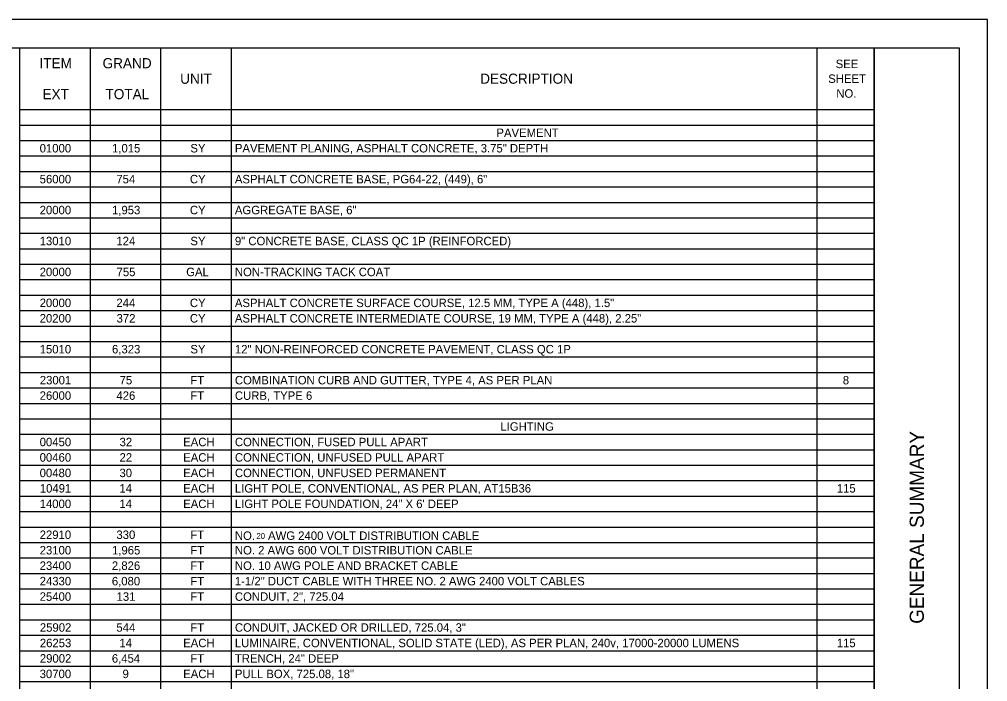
# Model space of a CAD drawing. Extents: x 0 to 34, y 0 to 22.
# Drawn here: x 16.92 to 34, y 10.33 to 22 of the extents above; entities that cross this region are included whole.
import ezdxf

# ---------------------------------------------------------------- set-up
doc = ezdxf.new("R2010")
doc.units = 0
for name, color, linetype in [('SH_Border', 7, 'Continuous'), ('SH_Cut_Line', 7, 'Continuous'), ('SH_Data', 7, 'Continuous'), ('SH_Text', 7, 'Continuous')]:
    doc.layers.add(name, color=color, linetype=linetype)

msp = doc.modelspace()

# ---------------------------------------------------------------- linework, layer by layer
at = {"layer": 'SH_Border'}
msp.add_line((32, 0.5), (32, 21.5), dxfattribs=at)
msp.add_lwpolyline([(1.5, 21.5), (33.5, 21.5), (33.5, 0.5), (1.5, 0.5)], close=True, dxfattribs=at)
at = {"layer": 'SH_Cut_Line'}
msp.add_lwpolyline([(0, 0), (34, 0), (34, 22), (0, 22)], close=True, dxfattribs=at)
at = {"layer": 'SH_Text'}
for p, q in [((16.919, 21.5), (19.411, 21.5)), ((16.919, 21.5), (16.919, 21.227)), ((18.165, 21.5), (18.165, 21.227)), ((19.411, 21.5), (20.657, 21.5)), ((19.411, 21.5), (19.411, 21.227)), ((20.657, 21.5), (32, 21.5)), ((20.657, 21.5), (20.657, 21.227)), ((30.988, 21.5), (30.988, 21.227)), ((32, 21.5), (32, 21.227)), ((16.919, 21.227), (16.919, 20.955)), ((18.165, 21.227), (18.165, 20.955)), ((19.411, 21.227), (19.411, 20.955)), ((20.657, 21.227), (20.657, 20.955)), ((30.988, 21.227), (30.988, 20.955)), ((32, 21.227), (32, 20.955)), ((16.919, 20.955), (16.919, 20.682)), ((18.165, 20.955), (18.165, 20.682)), ((19.411, 20.955), (19.411, 20.682)), ((20.657, 20.955), (20.657, 20.682)), ((30.988, 20.955), (30.988, 20.682)), ((32, 20.955), (32, 20.682)), ((16.919, 20.682), (16.919, 20.41)), ((18.165, 20.682), (18.165, 20.41)), ((19.411, 20.682), (19.411, 20.41)), ((20.657, 20.682), (20.657, 20.41)), ((30.988, 20.682), (30.988, 20.41)), ((32, 20.682), (32, 20.41)), ((16.919, 20.41), (19.411, 20.41)), ((16.919, 20.41), (16.919, 20.137)), ((18.165, 20.41), (18.165, 20.137)), ((19.411, 20.41), (20.657, 20.41)), ((19.411, 20.41), (19.411, 20.137)), ((20.657, 20.41), (32, 20.41)), ((20.657, 20.41), (20.657, 20.137)), ((30.988, 20.41), (30.988, 20.137)), ((32, 20.41), (32, 20.137)), ((16.919, 20.137), (19.411, 20.137)), ((16.919, 20.137), (16.919, 18.774)), ((18.165, 20.137), (18.165, 18.774)), ((19.411, 20.137), (20.657, 20.137)), ((19.411, 20.137), (19.411, 18.774)), ((20.657, 20.137), (32, 20.137)), ((20.657, 20.137), (20.657, 18.774)), ((30.988, 20.137), (30.988, 18.774)), ((32, 20.137), (32, 18.774)), ((16.919, 19.865), (19.411, 19.865)), ((19.411, 19.865), (20.657, 19.865)), ((20.657, 19.865), (32, 19.865)), ((16.919, 19.592), (19.411, 19.592)), ((19.411, 19.592), (20.657, 19.592)), ((20.657, 19.592), (32, 19.592)), ((16.919, 19.32), (19.411, 19.32)), ((19.411, 19.32), (20.657, 19.32)), ((20.657, 19.32), (32, 19.32)), ((16.919, 19.047), (19.411, 19.047)), ((19.411, 19.047), (20.657, 19.047)), ((20.657, 19.047), (32, 19.047)), ((16.919, 18.774), (19.411, 18.774)), ((16.919, 18.774), (16.919, 18.229)), ((18.165, 18.774), (18.165, 18.229)), ((19.411, 18.774), (20.657, 18.774)), ((19.411, 18.774), (19.411, 18.229)), ((20.657, 18.774), (32, 18.774)), ((20.657, 18.774), (20.657, 18.229)), ((30.988, 18.774), (30.988, 18.229)), ((32, 18.774), (32, 18.229)), ((16.919, 18.502), (19.411, 18.502)), ((19.411, 18.502), (20.657, 18.502)), ((20.657, 18.502), (32, 18.502)), ((16.919, 18.229), (19.411, 18.229)), ((16.919, 18.229), (16.919, 17.957)), ((18.165, 18.229), (18.165, 17.957)), ((19.411, 18.229), (20.657, 18.229)), ((19.411, 18.229), (19.411, 17.957)), ((20.657, 18.229), (32, 18.229)), ((20.657, 18.229), (20.657, 17.957)), ((30.988, 18.229), (30.988, 17.957)), ((32, 18.229), (32, 17.957)), ((16.919, 17.957), (19.411, 17.957)), ((16.919, 17.957), (16.919, 17.684)), ((18.165, 17.957), (18.165, 17.684)), ((19.411, 17.957), (20.657, 17.957)), ((19.411, 17.957), (19.411, 17.684)), ((20.657, 17.957), (32, 17.957)), ((20.657, 17.957), (20.657, 17.684)), ((30.988, 17.957), (30.988, 17.684)), ((32, 17.957), (32, 17.684)), ((16.919, 17.684), (19.411, 17.684)), ((16.919, 17.684), (16.919, 17.412)), ((18.165, 17.684), (18.165, 17.412)), ((19.411, 17.684), (20.657, 17.684)), ((19.411, 17.684), (19.411, 17.412)), ((20.657, 17.684), (32, 17.684)), ((20.657, 17.684), (20.657, 17.412)), ((30.988, 17.684), (30.988, 17.412)), ((32, 17.684), (32, 17.412)), ((16.919, 17.412), (19.411, 17.412)), ((16.919, 17.412), (16.919, 17.139)), ((18.165, 17.412), (18.165, 17.139)), ((19.411, 17.412), (20.657, 17.412)), ((19.411, 17.412), (19.411, 17.139)), ((20.657, 17.412), (32, 17.412)), ((20.657, 17.412), (20.657, 17.139)), ((30.988, 17.412), (30.988, 17.139)), ((32, 17.412), (32, 17.139)), ((16.919, 17.139), (19.411, 17.139)), ((16.919, 17.139), (16.919, 16.867)), ((18.165, 17.139), (18.165, 16.867)), ((19.411, 17.139), (20.657, 17.139)), ((19.411, 17.139), (19.411, 16.867)), ((20.657, 17.139), (32, 17.139)), ((20.657, 17.139), (20.657, 16.867)), ((30.988, 17.139), (30.988, 16.867)), ((32, 17.139), (32, 16.867)), ((16.919, 16.867), (19.411, 16.867)), ((16.919, 16.867), (16.919, 16.321)), ((18.165, 16.867), (18.165, 16.321)), ((19.411, 16.867), (20.657, 16.867)), ((19.411, 16.867), (19.411, 16.321)), ((20.657, 16.867), (32, 16.867)), ((20.657, 16.867), (20.657, 16.321)), ((30.988, 16.867), (30.988, 16.321)), ((32, 16.867), (32, 16.321)), ((16.919, 16.594), (19.411, 16.594)), ((19.411, 16.594), (20.657, 16.594)), ((20.657, 16.594), (32, 16.594)), ((16.919, 16.321), (19.411, 16.321)), ((16.919, 16.321), (16.919, 16.049)), ((18.165, 16.321), (18.165, 16.049)), ((19.411, 16.321), (20.657, 16.321)), ((19.411, 16.321), (19.411, 16.049)), ((20.657, 16.321), (32, 16.321)), ((20.657, 16.321), (20.657, 16.049)), ((30.988, 16.321), (30.988, 16.049)), ((32, 16.321), (32, 16.049)), ((16.919, 16.049), (19.411, 16.049)), ((16.919, 16.049), (16.919, 15.776)), ((18.165, 16.049), (18.165, 15.776)), ((19.411, 16.049), (20.657, 16.049)), ((19.411, 16.049), (19.411, 15.776)), ((20.657, 16.049), (32, 16.049)), ((20.657, 16.049), (20.657, 15.776)), ((30.988, 16.049), (30.988, 15.776)), ((32, 16.049), (32, 15.776)), ((16.919, 15.776), (19.411, 15.776)), ((16.919, 15.776), (16.919, 15.504)), ((18.165, 15.776), (18.165, 15.504)), ((19.411, 15.776), (20.657, 15.776)), ((19.411, 15.776), (19.411, 15.504)), ((20.657, 15.776), (32, 15.776)), ((20.657, 15.776), (20.657, 15.504)), ((30.988, 15.776), (30.988, 15.504)), ((32, 15.776), (32, 15.504)), ((16.919, 15.504), (19.411, 15.504)), ((16.919, 15.504), (16.919, 14.959)), ((18.165, 15.504), (18.165, 14.959)), ((19.411, 15.504), (20.657, 15.504)), ((19.411, 15.504), (19.411, 14.959)), ((20.657, 15.504), (32, 15.504)), ((20.657, 15.504), (20.657, 14.959)), ((30.988, 15.504), (30.988, 14.959)), ((32, 15.504), (32, 14.959)), ((16.919, 15.231), (19.411, 15.231)), ((19.411, 15.231), (20.657, 15.231)), ((20.657, 15.231), (32, 15.231)), ((16.919, 14.959), (19.411, 14.959)), ((16.919, 14.959), (16.919, 14.686)), ((18.165, 14.959), (18.165, 14.686)), ((19.411, 14.959), (20.657, 14.959)), ((19.411, 14.959), (19.411, 14.686)), ((20.657, 14.959), (32, 14.959)), ((20.657, 14.959), (20.657, 14.686)), ((30.988, 14.959), (30.988, 14.686)), ((32, 14.959), (32, 14.686)), ((16.919, 14.686), (19.411, 14.686)), ((16.919, 14.686), (16.919, 14.414)), ((18.165, 14.686), (18.165, 14.414)), ((19.411, 14.686), (20.657, 14.686)), ((19.411, 14.686), (19.411, 14.414)), ((20.657, 14.686), (32, 14.686)), ((20.657, 14.686), (20.657, 14.414)), ((30.988, 14.686), (30.988, 14.414)), ((32, 14.686), (32, 14.414)), ((16.919, 14.414), (19.411, 14.414)), ((16.919, 14.414), (16.919, 14.141)), ((18.165, 14.414), (18.165, 14.141)), ((19.411, 14.414), (20.657, 14.414)), ((19.411, 14.414), (19.411, 14.141)), ((20.657, 14.414), (32, 14.414)), ((20.657, 14.414), (20.657, 14.141)), ((30.988, 14.414), (30.988, 14.141)), ((32, 14.414), (32, 14.141)), ((16.919, 14.141), (19.411, 14.141)), ((16.919, 14.141), (16.919, 11.961)), ((18.165, 14.141), (18.165, 11.961)), ((19.411, 14.141), (20.657, 14.141)), ((19.411, 14.141), (19.411, 11.961)), ((20.657, 14.141), (32, 14.141)), ((20.657, 14.141), (20.657, 11.961)), ((30.988, 14.141), (30.988, 11.961)), ((32, 14.141), (32, 11.961)), ((16.919, 13.869), (19.411, 13.869)), ((19.411, 13.869), (20.657, 13.869)), ((20.657, 13.869), (32, 13.869)), ((16.919, 13.596), (19.411, 13.596)), ((19.411, 13.596), (20.657, 13.596)), ((20.657, 13.596), (32, 13.596)), ((16.919, 13.323), (19.411, 13.323)), ((19.411, 13.323), (20.657, 13.323)), ((20.657, 13.323), (32, 13.323)), ((16.919, 13.051), (19.411, 13.051)), ((19.411, 13.051), (20.657, 13.051)), ((20.657, 13.051), (32, 13.051)), ((16.919, 12.778), (19.411, 12.778)), ((19.411, 12.778), (20.657, 12.778)), ((20.657, 12.778), (32, 12.778)), ((16.919, 12.506), (19.411, 12.506)), ((19.411, 12.506), (20.657, 12.506)), ((20.657, 12.506), (32, 12.506)), ((16.919, 12.233), (19.411, 12.233)), ((19.411, 12.233), (20.657, 12.233)), ((20.657, 12.233), (32, 12.233)), ((16.919, 11.961), (19.411, 11.961)), ((16.919, 11.961), (16.919, 11.688)), ((18.165, 11.961), (18.165, 11.688)), ((19.411, 11.961), (20.657, 11.961)), ((19.411, 11.961), (19.411, 11.688)), ((20.657, 11.961), (32, 11.961)), ((20.657, 11.961), (20.657, 11.688)), ((30.988, 11.961), (30.988, 11.688)), ((32, 11.961), (32, 11.688)), ((16.919, 11.688), (19.411, 11.688)), ((16.919, 11.688), (16.919, 10.598)), ((18.165, 11.688), (18.165, 10.598)), ((19.411, 11.688), (20.657, 11.688)), ((19.411, 11.688), (19.411, 10.598)), ((20.657, 11.688), (32, 11.688)), ((20.657, 11.688), (20.657, 10.598)), ((30.988, 11.688), (30.988, 10.598)), ((32, 11.688), (32, 10.598)), ((16.919, 11.416), (19.411, 11.416)), ((19.411, 11.416), (20.657, 11.416)), ((20.657, 11.416), (32, 11.416)), ((16.919, 11.143), (19.411, 11.143)), ((19.411, 11.143), (20.657, 11.143)), ((20.657, 11.143), (32, 11.143)), ((16.919, 10.87), (19.411, 10.87)), ((19.411, 10.87), (20.657, 10.87)), ((20.657, 10.87), (32, 10.87)), ((16.919, 10.598), (19.411, 10.598)), ((16.919, 10.598), (16.919, 10.325)), ((18.165, 10.598), (18.165, 10.325)), ((19.411, 10.598), (20.657, 10.598)), ((19.411, 10.598), (19.411, 10.325)), ((20.657, 10.598), (32, 10.598)), ((20.657, 10.598), (20.657, 10.325)), ((30.988, 10.598), (30.988, 10.325)), ((32, 10.598), (32, 10.325)), ((16.919, 10.325), (19.411, 10.325)), ((16.919, 10.325), (16.919, 10.053)), ((18.165, 10.325), (18.165, 10.053)), ((19.411, 10.325), (20.657, 10.325)), ((19.411, 10.325), (19.411, 10.053)), ((20.657, 10.325), (32, 10.325)), ((20.657, 10.325), (20.657, 10.053)), ((30.988, 10.325), (30.988, 10.053)), ((32, 10.325), (32, 10.053))]:
    msp.add_line(p, q, dxfattribs=at)

# ---------------------------------------------------------------- texts
at = {"layer": 'SH_Data'}
msp.add_text('GENERAL SUMMARY', height=0.25, rotation=90, dxfattribs=at).set_placement((32.875, 11.344))
at = {"layer": 'SH_Text'}
for s, height, p in [('ITEM', 0.1791, (17.274, 21.138)), ('GRAND', 0.1791, (18.387, 21.138)), ('SEE ', 0.1493, (31.319, 21.141)), ('UNIT', 0.1791, (19.755, 20.865)), ('DESCRIPTION', 0.17911, (25.048, 20.865)), ('SHEET ', 0.1493, (31.188, 20.88)), ('EXT', 0.1791, (17.327, 20.593)), ('TOTAL', 0.1791, (18.438, 20.593)), ('NO.', 0.1493, (31.33, 20.619)), ('PAVEMENT', 0.1493, (25.335, 19.926)), ('01000', 0.1493, (17.277, 19.654)), ('1,015', 0.1493, (18.553, 19.654)), ('SY', 0.1493, (19.936, 19.654)), ('PAVEMENT PLANING, ASPHALT CONCRETE, 3.75" DEPTH', 0.14926, (20.721, 19.654)), ('56000', 0.1493, (17.277, 19.109)), ('754', 0.1493, (18.63, 19.109)), ('CY', 0.1493, (19.927, 19.109)), ('ASPHALT CONCRETE BASE, PG64-22, (449), 6"', 0.14926, (20.721, 19.109)), ('20000', 0.1493, (17.277, 18.564)), ('1,953', 0.1493, (18.553, 18.564)), ('CY', 0.1493, (19.927, 18.564)), ('AGGREGATE BASE, 6"', 0.14926, (20.721, 18.564)), ('13010', 0.1493, (17.277, 18.018)), ('124', 0.1493, (18.63, 18.018)), ('SY', 0.1493, (19.936, 18.018)), ('9" CONCRETE BASE, CLASS QC 1P (REINFORCED)', 0.14926, (20.721, 18.018)), ('20000', 0.1493, (17.277, 17.473)), ('755', 0.1493, (18.633, 17.473)), ('GAL', 0.1493, (19.862, 17.473)), ('NON-TRACKING TACK COAT', 0.14926, (20.721, 17.473)), ('ASPHALT CONCRETE SURFACE COURSE, 12.5 MM, TYPE A (448), 1.5"', 0.14926, (20.721, 16.928)), ('20000', 0.1493, (17.277, 16.928)), ('244', 0.1493, (18.63, 16.928)), ('CY', 0.1493, (19.927, 16.928)), ('20200', 0.1493, (17.277, 16.656)), ('372', 0.1493, (18.633, 16.656)), ('CY', 0.1493, (19.927, 16.656)), ('ASPHALT CONCRETE INTERMEDIATE COURSE, 19 MM, TYPE A (448), 2.25"', 0.14926, (20.721, 16.656)), ('15010', 0.1493, (17.277, 16.111)), ('6,323', 0.1493, (18.553, 16.111)), ('SY', 0.1493, (19.936, 16.111)), ('12" NON-REINFORCED CONCRETE PAVEMENT, CLASS QC 1P', 0.14926, (20.721, 16.111)), ('23001', 0.1493, (17.279, 15.565)), ('COMBINATION CURB AND GUTTER, TYPE 4, AS PER PLAN', 0.14926, (20.721, 15.565)), ('8', 0.149, (31.445, 15.565)), ('75', 0.1493, (18.687, 15.565)), ('FT', 0.1493, (19.934, 15.565)), ('26000', 0.1493, (17.277, 15.293)), ('426', 0.1493, (18.631, 15.293)), ('FT', 0.1493, (19.934, 15.293)), ('CURB, TYPE 6', 0.14926, (20.721, 15.293)), ('LIGHTING', 0.1493, (25.404, 14.748)), ('00450', 0.1493, (17.277, 14.475)), ('32', 0.1493, (18.686, 14.475)), ('EACH', 0.1493, (19.809, 14.475)), ('CONNECTION, FUSED PULL APART', 0.14926, (20.721, 14.475)), ('00460', 0.1493, (17.277, 14.203)), ('22', 0.1493, (18.686, 14.203)), ('EACH', 0.1493, (19.809, 14.203)), ('CONNECTION, UNFUSED PULL APART', 0.14926, (20.721, 14.203)), ('00480', 0.1493, (17.277, 13.93)), ('30', 0.1493, (18.684, 13.93)), ('EACH', 0.1493, (19.809, 13.93)), ('CONNECTION, UNFUSED PERMANENT', 0.14926, (20.721, 13.93)), ('10491', 0.1493, (17.279, 13.658)), ('14', 0.1493, (18.683, 13.658)), ('EACH', 0.1493, (19.809, 13.658)), ('LIGHT POLE, CONVENTIONAL, AS PER PLAN, AT15B36', 0.14926, (20.721, 13.658)), ('115', 0.1493, (31.339, 13.658)), ('14000', 0.1493, (17.277, 13.385)), ('14', 0.1493, (18.683, 13.385)), ('EACH', 0.1493, (19.809, 13.385)), ('LIGHT POLE FOUNDATION, 24" X 6\' DEEP', 0.14926, (20.721, 13.385)), ('22910', 0.1493, (17.277, 12.84)), ('330', 0.1493, (18.631, 12.84)), ('FT', 0.1493, (19.934, 12.84)), ('NO. ', 0.1493, (20.721, 12.824)), ('2', 0.104, (21.1, 12.841)), ('0', 0.104, (21.175, 12.841)), (' AWG 2400 VOLT DISTRIBUTION CABLE', 0.14926, (21.25, 12.824)), ('23100', 0.1493, (17.277, 12.567)), ('1,965', 0.1493, (18.553, 12.567)), ('FT', 0.1493, (19.934, 12.567)), ('NO. 2 AWG 600 VOLT DISTRIBUTION CABLE', 0.14926, (20.721, 12.567)), ('23400', 0.1493, (17.277, 12.295)), ('2,826', 0.1493, (18.551, 12.295)), ('FT', 0.1493, (19.934, 12.295)), ('NO. 10 AWG POLE AND BRACKET CABLE', 0.14926, (20.721, 12.295)), ('24330', 0.1493, (17.277, 12.022)), ('6,080', 0.1493, (18.55, 12.022)), ('FT', 0.1493, (19.934, 12.022)), ('1-1/2" DUCT CABLE WITH THREE NO. 2 AWG 2400 VOLT CABLES', 0.14926, (20.721, 12.022)), ('25400', 0.1493, (17.277, 11.75)), ('131', 0.1493, (18.633, 11.75)), ('FT', 0.1493, (19.934, 11.75)), ('CONDUIT, 2", 725.04', 0.14926, (20.721, 11.75)), ('25902', 0.1493, (17.28, 11.205)), ('544', 0.1493, (18.63, 11.205)), ('FT', 0.1493, (19.934, 11.205)), ('CONDUIT, JACKED OR DRILLED, 725.04, 3"', 0.14926, (20.721, 11.205)), ('26253', 0.1493, (17.28, 10.932)), ('14', 0.1493, (18.683, 10.932)), ('EACH', 0.1493, (19.809, 10.932)), ('LUMINAIRE, CONVENTIONAL, SOLID STATE (LED), AS PER PLAN, 240v, 17000-20000 LUMENS', 0.14926, (20.721, 10.932)), ('115', 0.1493, (31.339, 10.932)), ('29002', 0.1493, (17.28, 10.66)), ('6,454', 0.1493, (18.55, 10.66)), ('FT', 0.1493, (19.934, 10.66)), ('TRENCH, 24" DEEP', 0.14926, (20.721, 10.66)), ('30700', 0.1493, (17.277, 10.387)), ('9', 0.149, (18.739, 10.387)), ('EACH', 0.1493, (19.809, 10.387)), ('PULL BOX, 725.08, 18"', 0.14926, (20.721, 10.387))]:
    msp.add_text(s, height=height, dxfattribs=at).set_placement(p)

doc.saveas('drawing.dxf')
